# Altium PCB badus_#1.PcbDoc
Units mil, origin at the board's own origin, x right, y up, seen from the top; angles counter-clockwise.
Board outline 1397.64 x 1968.5 mil, 2 copper layers (Top Layer, Bottom Layer); 23 components, 13 nets, 121 pads, 4 vias.
Unrouted connection lines stored in the file: 2.
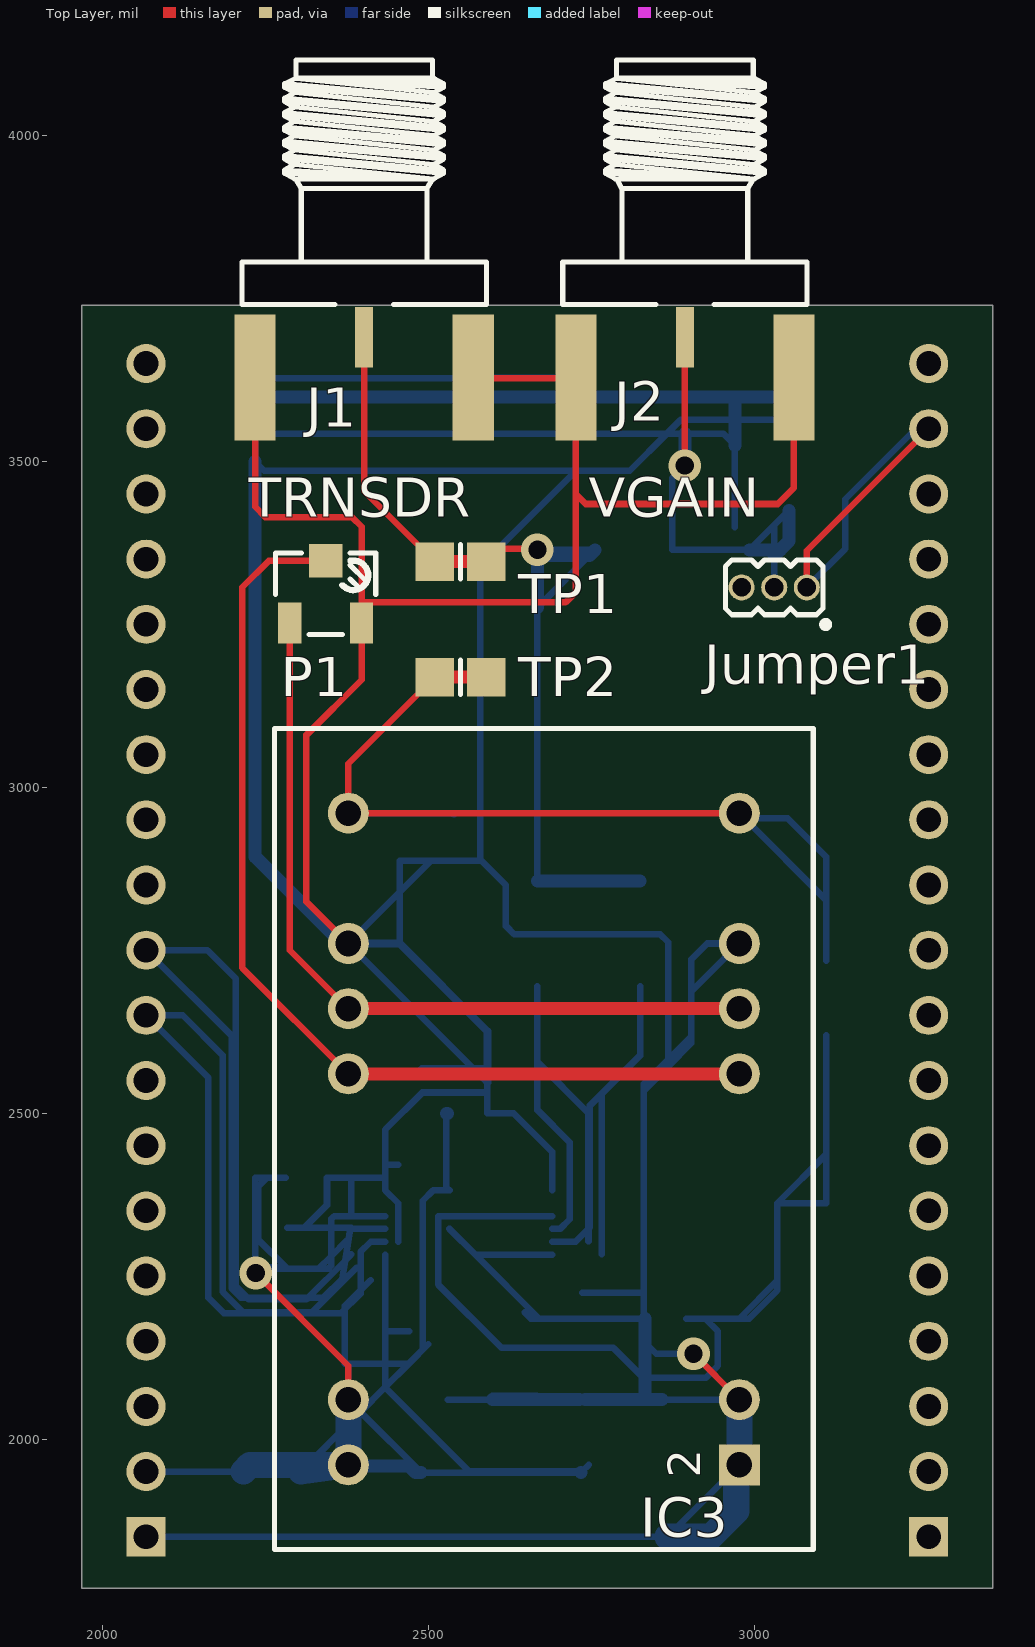
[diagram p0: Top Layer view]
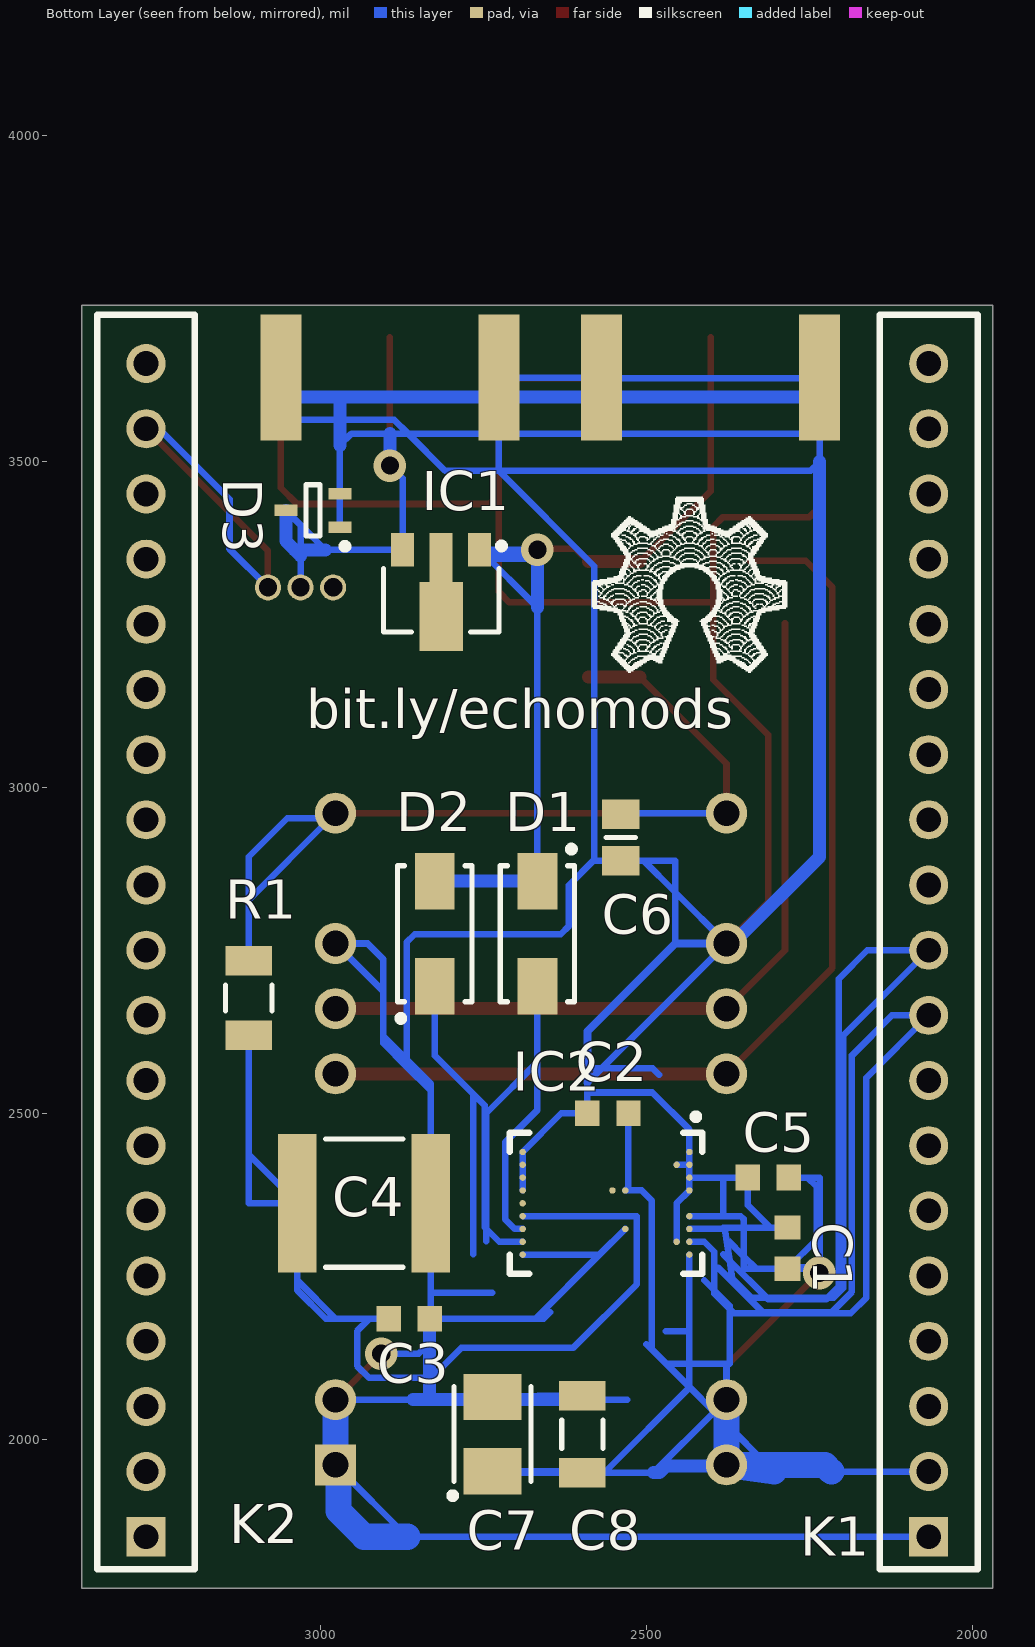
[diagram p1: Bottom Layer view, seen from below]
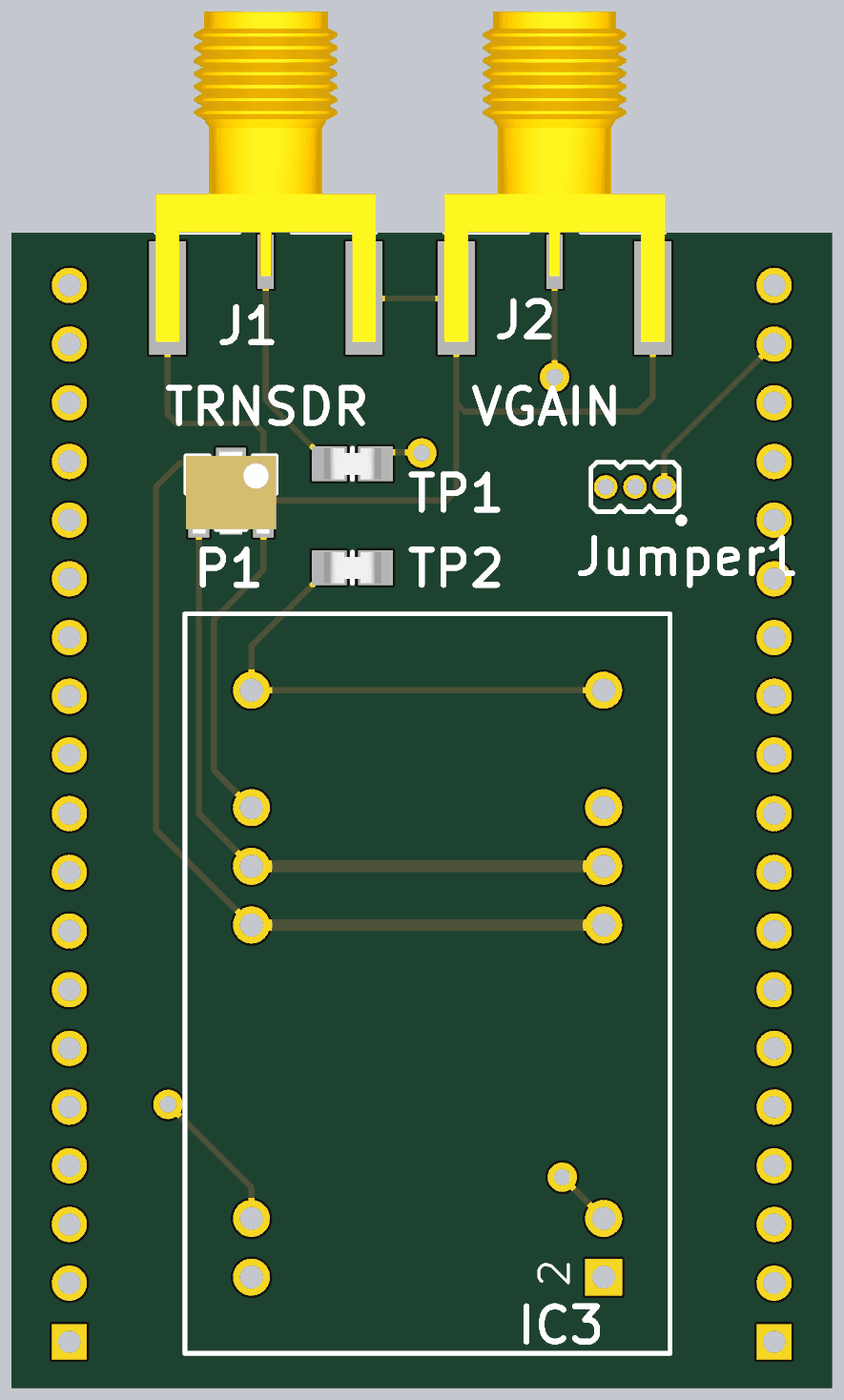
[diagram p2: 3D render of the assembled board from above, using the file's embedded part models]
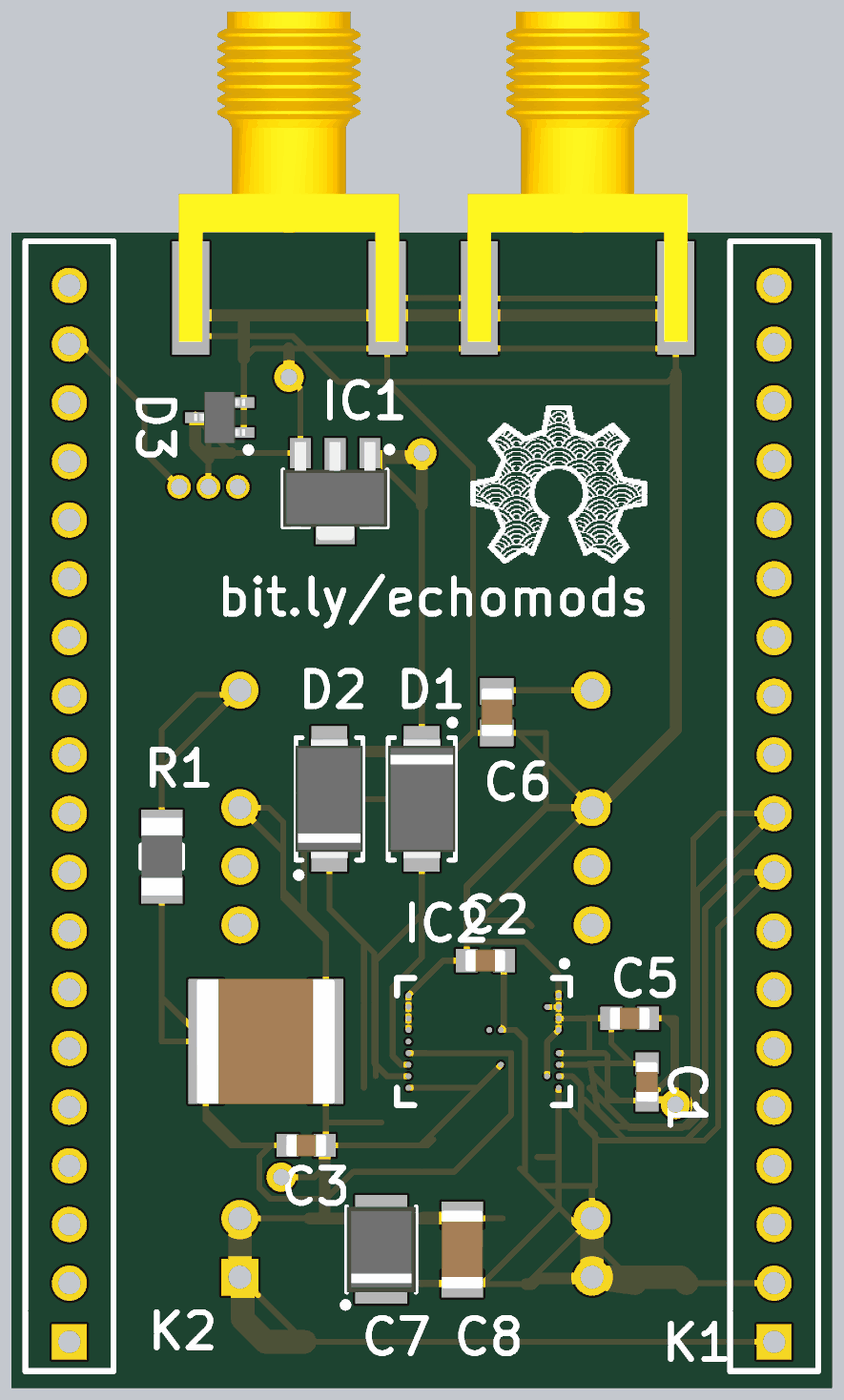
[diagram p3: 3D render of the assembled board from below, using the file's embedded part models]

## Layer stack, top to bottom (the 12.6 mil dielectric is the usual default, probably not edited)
Top Layer: signal copper 1.4
Dielectric: dielectric 12.6, FR-4, Dk 4.8
Bottom Layer: signal copper 1.4

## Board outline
1968.5,1771.65 3366.14,1771.65 3366.14,3740.16 1968.5,3740.16

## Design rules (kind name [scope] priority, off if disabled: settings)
Clearance [All] p1: gap=7
PolygonConnect [All] p1: connectstyle=Relief reliefconductorwidth=10 reliefentries=4 polygonreliefangle="90 Angle" airgapwidth=10
RoomDefinition us_#1sch [InComponentClass('us_#1sch')] p1: confinementstyle=ConfineIn formatcopy=TRUE lockcomponents=FALSE outline 0,0 2000,0 2000,1000 0,1000
RoutingVias [All] p1: holewidth=28 width=50 viastyle="Through Hole" minholewidth=28 minwidth=50 maxholewidth=28 maxwidth=50
SolderMaskExpansion [All] p1: expansion=4
Width [All] p1: maxlimit=40 minlimit=5 preferedwidth=10 minimp=50.000000 maximp=50.000000 favimp=50.000000
28 further rules are at their usual default settings.

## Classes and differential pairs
net class RF: NetD1_1 NetD3_3

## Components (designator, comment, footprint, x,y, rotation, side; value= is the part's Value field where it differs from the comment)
C1 "100nF" CAPC1608X87N 2283.46,2293.31 r270 bottom
C2 "100nF" CAPC1608X87N 2559.06,2500 r180 bottom
C3 "100nF" CAPC1608X87N 2864.17,2185.04 r0 bottom
C4 "1uF" CAPC5650X165N 2933.07,2362.2 r0 bottom
C5 "100nF" CAPC1608X87N 2312.99,2401.57 r180 bottom
C6 "4.7nF" CAPC2012X110N 2539.37,2923.23 r90 bottom
C7 "10uF" CAPMP3528X210N 2736.22,2007.87 r90 bottom
C8 "47uF" CAPC3216X180N 2598.43,2007.87 r270 bottom
D1 "ES1D" DIOM5027X244N 2667.32,2775.59 r270 bottom
D2 "ES1D" DIOM5027X244N 2824.8,2775.59 r90 bottom
D3 "BAT64-04W" SOT65P210X100-3N 3011.81,3425.2 r0 bottom
IC1 "MD0100N8-G" SOT89 2814.96,3287.4 r270 bottom
IC2 "HV7360LA-G" BGA22C50P9X14_500X700X105 2562,2362 r270 bottom
IC3 "R05-100B" PWS_RECOM_R05-100B 2677.17,2460.63 r90 top
J1 "SMA" AMPHENOL_132357-11 2401.57,3690.94 r270 top
J2 "SMA" AMPHENOL_132357-11 2893.7,3690.94 r270 top
Jumper1 "Family" SULLINS_GRPB031VWVN 3080.71,3307.09 r180 top
K1 "PLS_2.54mm-19" PLS_2.54mm-19 2066.93,1850.39 r180 bottom
K2 "PLS_2.54mm-19" PLS_2.54mm-19 3267.72,1850.39 r180 bottom
P1 "5k" TRIM_BOURNS_3223W 2342.52,3297.24 r0 top
R1 "4k7" RESC3216X65N 3110.24,2677.17 r90 bottom
TP1 "Test Point" NICOMATIC_C12000B 2549.21,3346.46 r0 top
TP2 "Test Point" NICOMATIC_C12000B 2549.21,3169.29 r180 top

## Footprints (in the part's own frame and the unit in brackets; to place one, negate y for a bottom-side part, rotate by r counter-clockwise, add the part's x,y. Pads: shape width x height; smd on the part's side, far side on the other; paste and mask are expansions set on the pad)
AMPHENOL_132357-11 [mm]
  rect 2.35x0.7 smd: 1(0,0)
  rect 4.9x1.6 smd: 2(1.575,4.25) 2(1.575,-4.25)
  rect 4.9x1.6 smd far side: 2(1.575,4.25) 2(1.575,-4.25)
  silkscreen extent -10.8,-4.76 -1.28,4.76, body extent -10.8,-4.76 3.48,4.76, height 4.08
BGA22C50P9X14_500X700X105 [mm] "BGA, 22-Leads, Body 5.00x7.00mmx1.05mm, Pitch 0.50mm"
  round 0.25 smd: A1(-2,3.25) A2(-1.5,3.25) A3(-1,3.25) A4(-0.5,3.25) A6(0.5,3.25) A7(1,3.25) A8(1.5,3.25) A9(2,3.25) B2(-1.5,2.75) B8(1.5,2.75) F4(-0.5,0.75) F7(1,0.75) G4(-0.5,0.25) P1(-2,-3.25) P2(-1.5,-3.25) P3(-1,-3.25) P4(-0.5,-3.25) P5(0,-3.25) P6(0.5,-3.25) P7(1,-3.25) P8(1.5,-3.25) P9(2,-3.25)
  silkscreen extent -3.5,-3.75 2.75,3.75
CAPC1608X87N [mm]
  rect 0.95x1 smd: 1(-0.8,0) 2(0.8,0)
  body extent -0.87,-0.47 0.88,0.48, height 0.87
CAPC2012X110N [mm]
  rect 1.15x1.45 smd: 1(-0.9,0) 2(0.9,0)
  silkscreen extent 0,-0.58 0,0.58, body extent -1.05,-0.67 1.05,0.68, height 1.1
CAPC3216X180N [mm]
  rect 1.15x1.8 smd: 1(-1.5,0) 2(1.5,0)
  silkscreen extent -0.55,-0.8 0.55,0.8, body extent -1.7,-0.9 1.7,0.9, height 1.8
CAPC5650X165N [mm]
  rect 1.5x5.4 smd: 1(-2.6,0) 2(2.6,0)
  silkscreen extent -1.5,-2.5 1.5,2.5, body extent -3,-2.7 3,2.7, height 1.65
CAPMP3528X210N [mm]
  rect 1.8x2.25 smd: 1(-1.45,0) 2(1.45,0)
  silkscreen extent -2.52,-1.5 1.85,1.68, body extent -1.85,-1.5 1.85,1.5, height 2.1
DIOM5027X244N [mm]
  rect 2.2x1.55 smd: 1(-2.05,0) 2(2.05,0)
  silkscreen extent -3.42,-1.45 2.65,1.45, body extent -2.6,-1.45 2.6,1.45, height 2.44
NICOMATIC_C12000B [mm]
  rect 1.5x1.5 smd: 1(-1,0) 1(1,0)
  silkscreen extent 0,-0.67 0,0.68, body extent -1.25,-0.67 1.25,0.68, height 1.5
PLS_2.54mm-19 [mil] "soldering pads"
  rect 60x60 hole 38: 1(0,0)
  round 60 hole 38: 2(0,100) 3(0,200) 4(0,300) 5(0,400) 6(0,500) 7(0,600) 8(0,700) 9(0,800) 10(0,900) 11(0,1000) 12(0,1100) 13(0,1200) 14(0,1300) 15(0,1400) 16(0,1500) 17(0,1600) 18(0,1700) 19(0,1800)
  silkscreen extent -75,-50 75,1875
PWS_RECOM_R05-100B [mm]
  rect 1.6x1.6 hole 1: 2(-12.7,-7.62)
  round 1.6 hole 1: 3(-10.16,-7.62) 8(2.54,-7.62) 9(5.08,-7.62) 10(7.62,-7.62) 12(12.7,-7.62) 13(12.7,7.62) 15(7.62,7.62) 16(5.08,7.62) 17(2.54,7.62) 22(-10.16,7.62) 23(-12.7,7.62)
  silkscreen extent -16,-10.5 16,10.5, body extent -16,-10.5 16,10.5, height 9.4
RESC3216X65N [mm]
  rect 1.15x1.8 smd: 1(-1.45,0) 2(1.45,0)
  silkscreen extent -0.5,-0.9 0.5,0.9, body extent -1.67,-0.87 1.68,0.88, height 0.65
SOT65P210X100-3N [mm]
  rect 0.9x0.45 smd: 1(-1.05,0.65) 2(-1.05,-0.65) 3(1.05,0)
  silkscreen extent -1.37,-1 0.28,1.52, body extent -1.1,-1.1 1.1,1.1, height 1
SOT89 [mm]
  rect 1.3x0.9 smd: 1(-1.965,1.5) 3(-1.965,-1.5)
  rect 1.9x0.9 smd: 2(-1.665,0)
  rect 2.7x1.7 smd: 2(0.635,0)
  silkscreen extent -2.24,-2.25 1.24,2.47, body extent -2.44,-2.25 1.81,2.25, height 1.6
SULLINS_GRPB031VWVN [mil]
  round 40 hole 28: 1(0,0) 2(50,0) 3(100,0)
  silkscreen extent -33,-42 125,61
TRIM_BOURNS_3223W [mm]
  rect 0.9x1.6 smd: 1(-1.4,-1.14) 3(1.4,-1.14)
  rect 1.3x1.3 smd: 2(0,1.29)
  silkscreen extent -1.95,-1.59 1.95,1.59, body extent -1.95,-1.81 1.95,1.81, height 4.16

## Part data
C1 C2 C3 C5: library part CC0603_100NF_50V_10%_X7R, "Non-polarised capacitor"
C4: library part CC2220_1UF_200V_10%_X7R, "Non-polarised capacitor"
C6: library part CC0805_4.7NF_250V_10%_X7R, "Non-polarised capacitor"
C7: library part CTE3528-21_10UF_16V_10%_LESR0800, "Polarised capacitor"
C8: library part CC1206_47UF_25V_20%_X5R, "Non-polarised capacitor"
D1 D2: "Diode"
D3: "Serial Diode"
IC1: "3-Ultra-Sound HV Switch 1=A 2=COM 3=B"
IC3: "Power Supply"
J1 J2: library part AMPHENOL_132357-11
Jumper1: library part "Connector 3 Male", "Connector 3 Male"
P1: library part TRIM_11T_5K_BOURNS_3223W-1-502E, "Trimming Potentiometer"
R1: library part R1206_4K7_1%_0.25W_100PPM, "Resistor - 1%"
TP1 TP2: library part NICOMATIC_C12000B

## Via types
v1: diameter 50, hole 28, Top Layer to Bottom Layer, 4 vias

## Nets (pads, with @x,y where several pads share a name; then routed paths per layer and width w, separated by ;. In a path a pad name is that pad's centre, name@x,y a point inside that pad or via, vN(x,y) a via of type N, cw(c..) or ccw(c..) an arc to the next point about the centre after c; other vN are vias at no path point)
AGND: C1.1 C2.1 C3.1 C4.1 C5.1 C6.1 C7.2 C8.1 D3.1 D3.2 IC2.A1 IC2.A2 IC2.A3 IC2.A4 IC2.B2 IC2.B8 IC2.F7 IC2.P1 IC2.P2 IC2.P3 IC2.P4 IC2.P9 IC3.2 IC3.3 IC3.10 IC3.15 J1.2 J2.2 K1.1 P1.3 | length 14852.1
  Top Layer w10: J1.2@2234.25,3628.94 2234.25,3430.75 2250,3415 2382.64,3415 2397.64,3400 2397.64,3284 ; IC3.15 2312.99,2824.8 2312.99,3080.71 2397.64,3165.35 P1.3 2397.64,3284 ; J1.2@2568.9,3628.94 2568.9,3628 J2.2@2726.38,3628 ; J2.2@2726.38,3628.94 J2.2@2726.38,3628 ; v1(2906.8,2131) IC3.3 ; J2.2@3061.02,3628.94 3061.02,3460.02 3036,3435 2741.38,3435 2726.38,3450 ; 2397.64,3284 2710.38,3284 2726.38,3300 2726.38,3450 ; 2726.38,3450 J2.2@2726.38,3628
  Bottom Layer w10: K1.1 2866.93,1850.39 2972.44,1955.9 IC3.2 ; J1.2@2234.25,3628.94 J1.2@2234.25,3628 ; C1.1 2309.98,2324.8 ; 2381.89,2324.8 2309.98,2324.8 ; 2381.89,2342.52 2381.89,2401.57 ; 2440.94,2165.35 2470.47,2165.35 ; IC2.B8 2453.73,2362 IC2.A4 IC2.A3 ; IC2.B2 IC2.A2 ; 2455.91,2760.63 2455.91,2839.37 ; 2480.32,2559.06 2490.16,2568.9 2568.9,2568.9 ; IC2.F7 2571.84,2283.26 ; 2590.55,2568.9 2568.9,2568.9 ; C8.1 2666,2066.93 2667.97,2064.96 C7.2 2832.68,2064.96 2854,2064.96 2858.33,2060.63 IC3.3 ; IC2.P9 2571.84,2283.26 ; IC2.P4 IC2.P3 IC2.P2 IC2.P1 2630.69,2500 C2.1 2590.55,2531 ; 2736.22,2224.41 2830.71,2224.41 ; v1(2906.8,2131) 2849.71,2131 2832.68,2148.03 2830.71,2150 C3.1@2830.71,2185.04 ; D3.1 D3.2 2970.47,3525 2952.47,3543 2866,3543 ; J2.2@3061.02,3628.94 3061.02,3599.41 3061.02,3564 2970.47,3564 2887,3564 2866,3543 ; J1.2@2234.25,3543 2234.25,3500 2248.25,3486 2726.38,3486 ; J1.2@2234.25,3543 2234.25,3599.41 J1.2@2234.25,3628 ; J1.2@2234.25,3543 J2.2@2726.38,3543 ; J1.2@2234.25,3628 2568.9,3628 2568.9,3628.94 2726.38,3628.94 2726.38,3599.41 J2.2@2726.38,3543 ; 2309.98,2324.8 2344.49,2359.32 C5.1 2381.89,2401.57 ; 2381.89,2401.57 2389,2401.57 2389.2,2401.37 IC2.A3 ; IC2.A3 IC2.A2 ; IC2.A2 IC2.A1 2434.05,2475.05 2491,2532 2589.55,2532 2590.55,2531 ; 2455.91,2839.37 2455.91,2887.8 2504.33,2887.8 ; 2455.91,2839.37 IC3.15 2568.9,2568.9 ; 2455.91,2839.37 2504.33,2887.8 ; 2504.33,2887.8 C6.1 2580,2887.8 ; 2568.9,2568.9 2590.55,2547.24 2590.55,2531 ; 2571.84,2283.26 2670.06,2185.04 C3.1@2830.71,2185.04 ; 2580,2887.8 2580,3339.62 2726.38,3486 ; 2580,2887.8 2581.2,2887.8 2619,2850 2619,2787.5 2631.5,2775 2855.5,2775 2868,2762.5 2868,2582.57 ; 2726.38,3486 2809,3486 2866,3543 ; 2726.38,3486 J2.2@2726.38,3543 ; J2.2@2726.38,3543 2866,3543 ; C3.1@2830.71,2185.04 C3.1 C3.1@2830.71,2187.01 ; C3.1@2830.71,2185.04 C3.1@2830.71,2187.01 ; C3.1@2830.71,2187.01 2830.71,2224.41 ; 2830.71,2224.41 C4.1 2830.71,2534.71 ; 2830.71,2534.71 2868,2572 ; 2830.71,2534.71 2830.71,2545.28 2868,2582.57 ; 2868,2572 2868,2582.57 ; 2868,2572 2903.54,2607.54 2903.54,2618.11 ; 2868,2582.57 2903.54,2618.11 ; 2903.54,2618.11 2903.54,2687.01 ; 2903.54,2687.01 IC3.10 2927.95,2760.63 2903.54,2736.22 2903.54,2687.01 ; 2529.53,2060.63 2598.43,2060.63 2529.53,2060.63
  Bottom Layer w12: IC3.15 2455.91,2760.63 2590.55,2625.98 2590.55,2568.9 2590.55,2547.24
  Bottom Layer w20: 2234.25,3500 2234.25,2893.7 IC3.15@2367.32,2760.63 ; C7.2@2740.55,2060.63 2858.33,2060.63 ; 2832.68,2064.96 2832.68,2148.03 C3.1 ; 2970.47,3525 2970.47,3564 2970.47,3599.41 ; 2970.47,3599.41 2726.38,3599.41 2234.25,3599.41 2647.64,3599.41 2970.47,3599.41 ; 2970.47,3599.41 3061.02,3599.41 2970.47,3599.41 ; C8.1@2598.43,2060.63 2731.89,2060.63 C8.1@2598.43,2060.63
  Bottom Layer w40: 2866.93,1850.39 2933.07,1850.39 2972.44,1889.76 2972.44,1955.9 IC3.2 IC3.3
HVOUT: C6.2 IC3.12 IC3.13 R1.2 TP2.1 | length 1602.7
  Top Layer w10: TP2.1@2509.84,3169.29 2377.17,3036.62 IC3.13 IC3.12
  Top Layer w20: TP2.1@2509.84,3169.29 TP2.1@2588.58,3169.29
  Bottom Layer w10: IC3.13 2537.4,2960.63 C6.2 ; IC3.12 IC3.12@2985.04,2952.76 ; R1.2 3110.24,2827.56 ; IC3.12@2985.04,2952.76 3051.18,2952.76 3110.24,2893.7 3110.24,2827.56 ; IC3.12@2985.04,2952.76 3110.24,2827.56
NetC3_2: C3.2 C4.2 IC2.P6 R1.1 | length 1731.1
  Bottom Layer w10: 2647.64,2194.88 2657.48,2185.04 2706.06,2185.04 ; IC2.P6 2515,2342 2515,2237.5 2612.5,2140 2784,2140 2830,2094 2925.5,2094 2944,2112.5 2944,2166.04 2925,2185.04 ; C3.2 2925,2185.04 ; R1.1 3110.24,2437.01 ; 2925,2185.04 2977,2185.04 ; 2977,2185.04 3035.43,2243.47 ; 2977,2185.04 2992.13,2185.04 3035.43,2228.35 3035.43,2243.47 ; 3035.43,2243.47 C4.2 ; C4.2 3110.24,2362.2 3110.24,2437.01 ; C4.2 3110.24,2437.01
NetD1_1: D1.1 D2.2 IC1.1 J1.1 TP1.1 | length 1599.1
  Top Layer w10: J1.1 2401.57,3454.72 TP1.1@2509.84,3346.46 ; TP1.1@2588.58,3346.46 2608.27,3366.14 2665.94,3366.14 v1(2667.32,3364.76)
  Top Layer w20: TP1.1@2509.84,3346.46 TP1.1@2588.58,3346.46
  Bottom Layer w10: D1.1 2667.32,3276.18 IC1.1 v1(2667.32,3364.76)
  Bottom Layer w20: D1.1 D2.2 ; 2667.32,3276.18 v1@2667.32,3356.3 ; IC1.1 IC1.1@2747.44,3356.3 ; v1@2667.32,3356.3 IC1.1@2747.44,3356.3 ; v1@2667.32,3356.3 IC1.1@2747.44,3356.3
NetD1_2: D1.2 IC2.P7 | length 718.9
  Bottom Layer w10: D1.2 2667.32,2578.74 ; IC2.P7 2702.13,2322.63 2717,2337.5 2717,2455.32 2667.32,2505 2667.32,2578.74 ; 2745.75,2303.46 2745.75,2500.32 2667.32,2578.74
NetD2_1: D2.1 IC2.P8 | length 798.9
  Bottom Layer w10: IC2.P8 2725.94,2302.94 2748,2325 2748,2512.2 2824.8,2589 ; 2765.75,2283.46 2765.75,2529.53 2824.8,2588.58 2824.8,2589 ; D2.1 2824.8,2687.01 2824.8,2589
NetD3_3: D3.3 IC1.3 J2.1 Jumper1.2 | length 809.7
  Top Layer w10: v1(2893.61,3494) 2893.7,3494.09 J2.1
  Bottom Layer w10: v1(2893.61,3494) 2874.02,3474.41 IC1.3 2992.72,3364.76 3030.71,3402.75 ; Jumper1.2 3030.71,3355.51 3030.71,3364.76 3030.71,3402.75 ; D3.3 3030.71,3402.75
  Bottom Layer w20: v1(2893.61,3494) 2893.7,3494.09 2893.7,3543.31 ; 2992.72,3364.76 3030.71,3364.76 3039.96,3364.76 ; 3030.71,3355.51 3039.96,3364.76 ; D3.3 3053.15,3377.95 3039.96,3364.76
NetIC3_8: IC3.8 IC3.17 P1.2 | length 1558.7
  Top Layer w10: P1.2 2255.51,3348.03 2214.57,3307.09 2214.57,2723.23 IC3.17
  Top Layer w20: IC3.17 IC3.8
NetIC3_9: IC3.9 IC3.16 P1.1 | length 1228.9
  Top Layer w10: P1.1 2287.4,2750.39 IC3.16
  Top Layer w20: IC3.16 IC3.9
PULSE_A: IC2.A8 K1.9 | length 1590.6
  Bottom Layer w10: 2390.17,2263.46 2321.28,2194.57 2216.13,2194.57 2184.72,2225.97 2184.72,2588.9 2123.23,2650.39 K1.9 2162.5,2554.82 2162.5,2217 2186.39,2193.11 2365.61,2193.11 2396,2223.5 2396,2287.5 2411.44,2302.94 IC2.A8
PULSE_B: IC2.A7 K1.10 | length 1734.6
  Bottom Layer w10: 2381.89,2283.46 2372.38,2273.95 ; IC2.A7 2380,2322.63 2372.38,2273.95 ; 2221.7,2217.28 2204.72,2234.25 2204.72,2706.69 2161.02,2750.39 K1.10 2198,2619.32 2198,2231.78 2212.5,2217.28 2221.7,2217.28 ; 2221.7,2217.28 2224.41,2214.57 2312.99,2214.57 2315.7,2217.28 ; 2221.7,2217.28 2315.7,2217.28 ; 2315.7,2217.28 2339.28,2217.28 2368,2246 2372.38,2273.95 ; 2315.7,2217.28 2372.38,2273.95
VDD_5V: C1.2 C2.2 C5.2 C7.1 C8.2 IC2.A6 IC2.A9 IC2.F4 IC3.22 IC3.23 K1.2 | length 3655.1
  Top Layer w10: v1(2235,2255) 2377.17,2112.83 IC3.22
  Bottom Layer w10: K1.2 2216.14,1950.39 2304.39,1950.39 2314.63,1960.63 2377.17,2023.17 IC3.22@2395.9,2041.9 ; v1(2235,2255) 2241.81,2261.81 C1.2 ; C5.2 2252.8,2401.57 ; 2372.05,2116.14 2372.05,2204.72 2411.42,2244.09 ; 2374.9,2304.76 2351,2280.86 ; 2377.17,2111.02 IC3.22 IC3.22@2395.9,2041.9 ; 2377.17,2116.14 2434.05,2116.14 ; IC2.A9 2434.05,2116.14 ; IC2.A6 2355.32,2342.32 2351,2338 2351,2280.86 ; 2500,2145.67 2470.47,2116.14 2470.14,2116.14 ; C2.2 2527.56,2386.6 IC2.F4 2507.19,2381.69 2491.5,2366 2491.5,2137.5 2470.14,2116.14 ; C7.1@2746.06,1960.63 C7.1 ; 2252.8,2401.57 2238.72,2387.5 2238.72,2306.55 C1.2@2281.5,2263.78 ; 2252.8,2401.57 2234.25,2401.57 2234.25,2263.78 C1.2@2281.5,2263.78 ; C1.2@2281.5,2263.78 C1.2 ; C1.2 2331.95,2261.81 ; 2331.95,2261.81 2346.81,2261.81 2351,2266 2351,2280.86 ; 2331.95,2261.81 2351,2280.86 ; IC3.22@2395.9,2041.9 2434.05,2080.05 ; IC3.22@2395.9,2041.9 2488.98,1948.82 C8.2 C7.1@2734.25,1948.82 ; 2434.05,2080.05 2470.14,2116.14 ; 2434.05,2080.05 2434.05,2079.24 2562.5,1950.79 C7.1 ; 2434.05,2080.05 2434.05,2116.14 ; 2434.05,2116.14 2470.14,2116.14 ; C7.1@2734.25,1948.82 C7.1 ; C7.1@2734.25,1948.82 C7.1
  Bottom Layer w20: IC3.23@2379.13,1958.66 2470.47,1958.66 2480.31,1948.82 2488.98,1948.82 ; C2.2 C2.2@2529.53,2500
  Bottom Layer w40: K1.2@2065.35,1948.82 K1.2 ; 2216.14,1950.39 2226.38,1960.63 2314.63,1960.63 IC3.23 ; 2304.39,1950.39 IC3.23 ; IC3.22 2377.17,2023.17 IC3.23
"VGA IN": Jumper1.1 K2.18 | length 633.4
  Top Layer w10: Jumper1.1 3080.71,3363.39 K2.18
  Bottom Layer w10: Jumper1.1 3139.76,3366.14 3139.76,3442.13 K2.18@3248.03,3550.39
pads on no net: IC1.2 IC2.G4 IC2.P5 Jumper1.3 K1.3 K1.4 K1.5 K1.6 K1.7 K1.8 K1.11 K1.12 K1.13 K1.14 K1.15 K1.16 K1.17 K1.18 K1.19 K2.1 K2.2 K2.3 K2.4 K2.5 K2.6 K2.7 K2.8 K2.9 K2.10 K2.11 K2.12 K2.13 K2.14 K2.15 K2.16 K2.17 K2.19

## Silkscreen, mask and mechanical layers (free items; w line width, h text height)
Top Overlay:
  text "TRNSDR" at 2224.41,3415.35 h60
  text "VGAIN" at 2746.06,3415.35 h60
Bottom Overlay:
  drawing of 1520 lines, arcs and shapes, not listed
  text "bit.ly/echomods" at 3021.65,3090.55 h60
Mechanical 1:
  lines w10: 1968.5,1771.65 3366.14,1771.65 3366.14,1914.37 3366.14,2121.06 3366.14,2283.46 3366.14,2529.53 3366.14,2982.28 3366.14,3228.35 3366.14,3390.75 3366.14,3597.44 3366.14,3740.16 1968.5,3740.16 1968.5,1771.65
